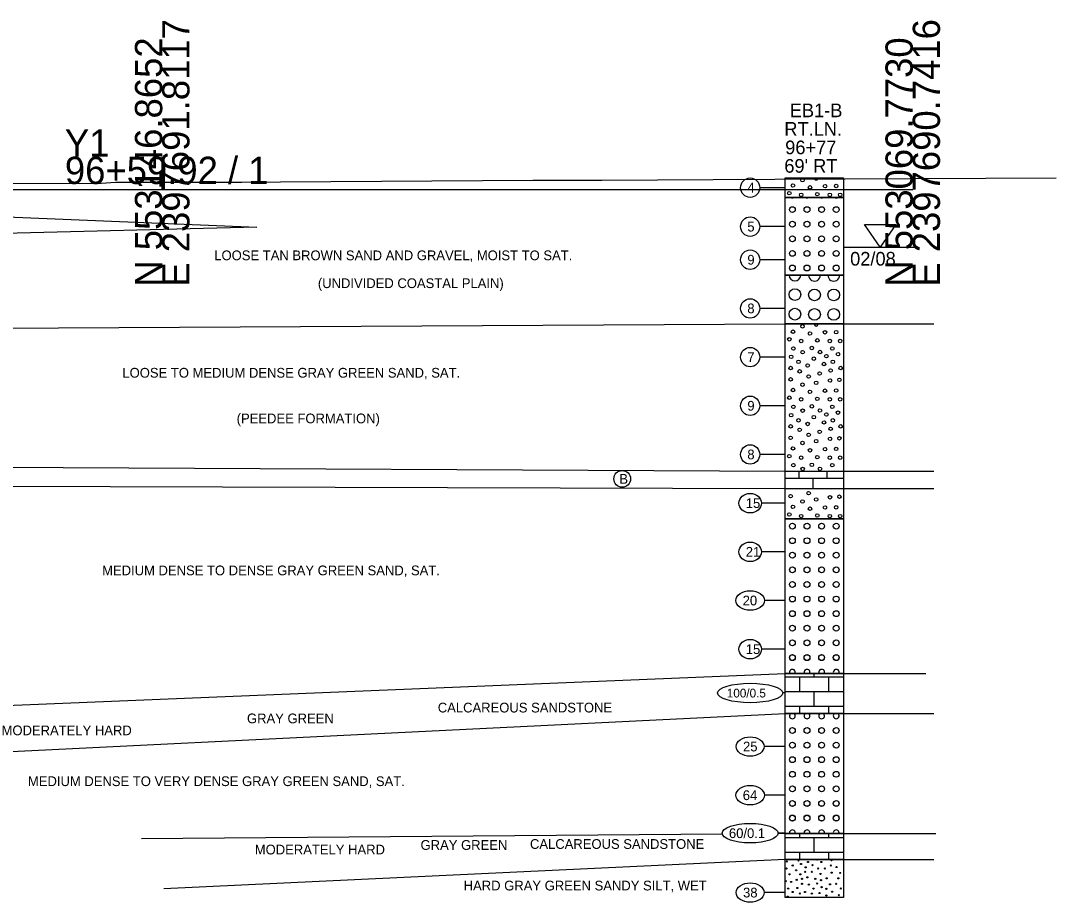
# Model space of a CAD drawing. Extents: x -26 to 164, y -74 to 517.
# Drawn here: x 57.6 to 164, y -73.2 to 17.3 of the extents above; entities that cross this region are included whole.
import ezdxf

# ---------------------------------------------------------------- set-up
doc = ezdxf.new("R2010")
doc.units = 0
for name, color, linetype in [('Exist XS Ground Line', 7, 'Continuous'), ('Old_Level_63', 7, 'Continuous'), ('Prop Road Sect_ Boring - Header Labels from Geopak', 7, 'Continuous'), ('Prop Road Sect_ Boring - Material (Outline)', 7, 'Continuous'), ('Prop Road Sect_ Boring - Peripheral (24 Hr GrdWtr Date)', 7, 'Continuous'), ('Prop Road Sect_ Boring - Peripheral (SPT Oval + Leader)', 7, 'Continuous'), ('Prop Road Sect_ Boring - Peripheral (SPT Tx)', 7, 'Continuous'), ('Prop Road Sect_ Material - Contact (General - Minor)', 7, 'Continuous'), ('Prop Road Sect_ Material - Tx (Composite Desc)', 7, 'Continuous'), ('Water Mark (24 Hr) Cell', 7, 'Continuous')]:
    doc.layers.add(name, color=color, linetype=linetype)

msp = doc.modelspace()

# ---------------------------------------------------------------- linework, layer by layer
at = {"layer": 'Exist XS Ground Line'}
for points in [[(135.07, 1.05), (163.98, 1.19)], [(0, 0.86), (2, 0.88), (15.97, 0.78), (18.54, 0.63), (22.6, 0.64), (32.39, 0.61), (35.94, 0.6), (40.49, 0.57), (65.87, 0.64), (67.35, 0.72), (72.13, 0.73), (80.32, 0.75), (84.27, 0.77), (110.22, 0.93), (117.29, 0.95), (128.72, 1.02), (135.07, 1.05)]]:
    msp.add_lwpolyline(points, dxfattribs=at)
at = {"layer": 'Old_Level_63'}
for p, q in [((72.13, 0), (72.13, 3.35)), ((0, 0), (72.13, 0)), ((72.13, 0), (149.23, 0))]:
    msp.add_line(p, q, dxfattribs=at)
at = {"layer": 'Prop Road Sect_ Boring - Material (Outline)'}
for p, q in [((136.13, -28.93), (142.12, -28.93)), ((136.13, -30.73), (142.12, -30.73)), ((139.12, -50.08), (139.12, -49.72)), ((136.13, -50.08), (142.12, -50.08)), ((137.62, -51.58), (137.62, -50.08)), ((140.62, -51.58), (140.62, -50.08)), ((142.12, -50.08), (142.13, -50.08)), ((136.13, -51.58), (142.12, -51.58)), ((139.12, -53.08), (139.12, -51.58)), ((142.12, -51.58), (142.13, -51.58)), ((136.13, -53.08), (142.12, -53.08)), ((137.62, -53.83), (137.62, -53.08)), ((140.62, -53.83), (140.62, -53.08)), ((142.12, -53.08), (142.13, -53.08)), ((142.12, -65.08), (142.13, -65.08)), ((136.13, -66.58), (142.12, -66.58)), ((137.62, -66.58), (137.62, -66.17)), ((139.12, -68.08), (139.12, -66.58)), ((140.62, -66.58), (140.62, -66.09)), ((142.12, -66.58), (142.13, -66.58)), ((136.13, -68.08), (142.12, -68.08)), ((137.62, -68.83), (137.62, -68.08)), ((140.62, -68.83), (140.62, -68.08)), ((142.12, -68.08), (142.13, -68.08))]:
    msp.add_line(p, q, dxfattribs=at)
for points in [[(136.13, 1.17), (142.13, 1.17), (142.13, -0.83), (136.13, -0.83)], [(136.13, -0.83), (142.13, -0.83), (142.13, -8.83), (136.13, -8.83)], [(136.13, -8.83), (142.13, -8.83), (142.13, -13.83), (136.13, -13.83)], [(136.13, -13.83), (142.13, -13.83), (142.13, -33.83), (136.13, -33.83)], [(136.13, -33.83), (142.13, -33.83), (142.13, -49.72), (136.13, -49.72)], [(136.13, -49.72), (142.13, -49.72), (142.13, -53.83), (136.13, -53.83)], [(136.13, -53.83), (142.13, -53.83), (142.13, -66.17), (136.13, -66.17)], [(136.13, -66.17), (142.13, -66.17), (142.13, -68.83), (136.13, -68.83)], [(136.13, -68.83), (142.13, -68.83), (142.13, -72.73), (136.13, -72.73)]]:
    msp.add_lwpolyline(points, close=True, dxfattribs=at)
for centre, radius in [((137.91, 0.94), 0.18), ((136.93, 0.39), 0.18), ((138.67, 0.2), 0.18), ((140.22, 0.32), 0.18), ((141.37, 0.34), 0.18), ((136.55, -0.39), 0.18), ((137.77, -0.56), 0.18), ((139.43, -0.5), 0.18), ((140.72, -0.56), 0.18), ((141.78, -0.56), 0.18), ((136.87, -2.08), 0.3), ((138.37, -2.08), 0.3), ((139.87, -2.08), 0.3), ((141.37, -2.08), 0.3), ((136.87, -3.58), 0.3), ((138.37, -3.58), 0.3), ((139.87, -3.58), 0.3), ((141.37, -3.58), 0.3), ((136.87, -5.08), 0.3), ((138.37, -5.08), 0.3), ((139.87, -5.08), 0.3), ((141.37, -5.08), 0.3), ((136.87, -6.58), 0.3), ((138.37, -6.58), 0.3), ((139.87, -6.58), 0.3), ((141.37, -6.58), 0.3), ((136.87, -8.08), 0.3), ((138.37, -8.08), 0.3), ((139.87, -8.08), 0.3), ((141.37, -8.08), 0.3), ((137.13, -10.81), 0.6), ((139.14, -10.84), 0.6), ((141.12, -10.84), 0.6), ((137.13, -12.82), 0.6), ((139.14, -12.85), 0.6), ((141.12, -12.85), 0.6), ((136.93, -14.62), 0.18), ((137.91, -14.07), 0.18), ((138.67, -14.8), 0.18), ((140.22, -14.68), 0.18), ((141.37, -14.67), 0.18), ((136.55, -15.4), 0.18), ((137.77, -15.57), 0.18), ((139.43, -15.51), 0.18), ((140.72, -15.57), 0.18), ((141.78, -15.57), 0.18), ((136.97, -16.34), 0.18), ((137.92, -16.73), 0.18), ((138.86, -16.29), 0.18), ((139.7, -16.71), 0.18), ((140.36, -17.13), 0.18), ((140.97, -16.34), 0.18), ((141.56, -16.93), 0.18), ((136.74, -17.21), 0.18), ((137.5, -17.72), 0.18), ((138.43, -18.1), 0.18), ((139.07, -17.4), 0.18), ((140.12, -17.94), 0.18), ((141.02, -17.72), 0.18), ((136.69, -18.35), 0.18), ((137.61, -18.7), 0.18), ((138.54, -19.22), 0.18), ((139.67, -18.91), 0.18), ((140.8, -18.6), 0.18), ((141.83, -18.35), 0.18), ((136.69, -19.52), 0.18), ((137.91, -20.07), 0.18), ((139.31, -19.87), 0.18), ((140.74, -19.63), 0.18), ((141.7, -19.57), 0.18), ((136.55, -21.4), 0.18), ((136.93, -20.61), 0.18), ((138.67, -20.8), 0.18), ((140.22, -20.68), 0.18), ((141.37, -20.66), 0.18), ((136.97, -22.34), 0.18), ((137.77, -21.56), 0.18), ((138.86, -22.29), 0.18), ((139.43, -21.51), 0.18), ((140.72, -21.56), 0.18), ((140.97, -22.34), 0.18), ((141.78, -21.56), 0.18), ((136.74, -23.2), 0.18), ((137.92, -22.73), 0.18), ((139.07, -23.4), 0.18), ((139.7, -22.71), 0.18), ((140.36, -23.12), 0.18), ((141.56, -22.93), 0.18), ((136.69, -24.35), 0.18), ((137.5, -23.72), 0.18), ((138.43, -24.1), 0.18), ((140.12, -23.94), 0.18), ((140.8, -24.59), 0.18), ((141.02, -23.72), 0.18), ((141.83, -24.35), 0.18), ((136.69, -25.52), 0.18), ((137.61, -24.7), 0.18), ((138.54, -25.22), 0.18), ((139.67, -24.91), 0.18), ((140.74, -25.63), 0.18), ((141.7, -25.57), 0.18), ((136.93, -26.61), 0.18), ((137.91, -26.06), 0.18), ((139.31, -25.87), 0.18), ((140.22, -26.68), 0.18), ((141.37, -26.66), 0.18), ((136.55, -27.4), 0.18), ((137.77, -27.56), 0.18), ((138.67, -26.8), 0.18), ((139.43, -27.51), 0.18), ((140.72, -27.56), 0.18), ((141.78, -27.56), 0.18), ((136.97, -28.33), 0.18), ((137.92, -28.72), 0.18), ((138.86, -28.29), 0.18), ((139.7, -28.7), 0.18), ((140.97, -28.33), 0.18), ((136.69, -31.51), 0.18), ((137.91, -32.06), 0.18), ((138.54, -31.21), 0.18), ((139.31, -31.86), 0.18), ((140.74, -31.63), 0.18), ((141.7, -31.57), 0.18), ((136.93, -32.61), 0.18), ((138.67, -32.8), 0.18), ((140.22, -32.68), 0.18), ((141.37, -32.66), 0.18), ((136.55, -33.39), 0.18), ((137.77, -33.56), 0.18), ((139.43, -33.5), 0.18), ((140.72, -33.56), 0.18), ((141.78, -33.56), 0.18), ((136.87, -34.59), 0.3), ((138.37, -34.59), 0.3), ((139.87, -34.59), 0.3), ((141.37, -34.59), 0.3), ((136.87, -36.09), 0.3), ((138.37, -36.09), 0.3), ((139.87, -36.09), 0.3), ((141.37, -36.09), 0.3), ((136.87, -37.58), 0.3), ((138.37, -37.58), 0.3), ((139.87, -37.58), 0.3), ((141.37, -37.58), 0.3), ((136.87, -39.08), 0.3), ((138.37, -39.08), 0.3), ((139.87, -39.08), 0.3), ((141.37, -39.08), 0.3), ((136.87, -40.58), 0.3), ((138.37, -40.58), 0.3), ((139.87, -40.58), 0.3), ((141.37, -40.58), 0.3), ((136.87, -42.08), 0.3), ((138.37, -42.08), 0.3), ((139.87, -42.08), 0.3), ((141.37, -42.08), 0.3), ((136.87, -43.58), 0.3), ((138.37, -43.58), 0.3), ((139.87, -43.58), 0.3), ((141.37, -43.58), 0.3), ((136.87, -45.08), 0.3), ((138.37, -45.08), 0.3), ((139.87, -45.08), 0.3), ((141.37, -45.08), 0.3), ((136.87, -46.58), 0.3), ((138.37, -46.58), 0.3), ((139.87, -46.58), 0.3), ((141.37, -46.58), 0.3), ((136.87, -48.08), 0.3), ((136.87, -48.1), 0.3), ((138.37, -48.08), 0.3), ((138.37, -48.1), 0.3), ((139.87, -48.08), 0.3), ((139.87, -48.1), 0.3), ((141.37, -48.08), 0.3), ((141.37, -48.1), 0.3), ((136.87, -55.58), 0.3), ((138.37, -55.58), 0.3), ((139.87, -55.58), 0.3), ((141.37, -55.58), 0.3), ((136.87, -57.08), 0.3), ((138.37, -57.08), 0.3), ((139.87, -57.08), 0.3), ((141.37, -57.08), 0.3), ((136.87, -58.58), 0.3), ((138.37, -58.58), 0.3), ((139.87, -58.58), 0.3), ((141.37, -58.58), 0.3), ((136.87, -60.08), 0.3), ((138.37, -60.08), 0.3), ((139.87, -60.08), 0.3), ((141.37, -60.08), 0.3), ((136.87, -61.58), 0.3), ((138.37, -61.58), 0.3), ((139.87, -61.58), 0.3), ((141.37, -61.58), 0.3), ((136.87, -63.07), 0.3), ((136.87, -63.08), 0.3), ((138.37, -63.07), 0.3), ((138.37, -63.08), 0.3), ((139.87, -63.07), 0.3), ((139.87, -63.08), 0.3), ((141.37, -63.07), 0.3), ((141.37, -63.08), 0.3), ((136.87, -64.57), 0.3), ((136.87, -64.59), 0.3), ((138.37, -64.57), 0.3), ((138.37, -64.59), 0.3), ((139.87, -64.57), 0.3), ((139.87, -64.59), 0.3), ((141.37, -64.57), 0.3), ((141.37, -64.59), 0.3), ((136.3, -69.04), 0.06), ((137.5, -68.93), 0.06), ((138.48, -69.09), 0.06), ((139.84, -69.09), 0.06), ((136.25, -69.75), 0.06), ((136.9, -69.45), 0.06), ((137.26, -69.94), 0.06), ((137.75, -69.29), 0.06), ((138.18, -70.1), 0.06), ((138.24, -69.64), 0.06), ((138.86, -70.1), 0.06), ((138.94, -69.42), 0.06), ((139.52, -69.75), 0.06), ((140.2, -69.75), 0.06), ((140.82, -69.45), 0.06), ((140.91, -70.19), 0.06), ((141.4, -69.61), 0.06), ((141.78, -70.21), 0.06), ((136.19, -71.06), 0.06), ((136.57, -70.35), 0.06), ((136.74, -71.14), 0.06), ((137.31, -70.92), 0.06), ((137.69, -70.35), 0.06), ((137.86, -70.81), 0.06), ((137.86, -71.33), 0.06), ((138.4, -70.67), 0.06), ((139.22, -70.81), 0.06), ((139.41, -71.3), 0.06), ((139.76, -70.32), 0.06), ((139.81, -70.95), 0.06), ((140.39, -70.76), 0.06), ((141.37, -71.33), 0.06), ((141.59, -70.76), 0.06), ((136.44, -71.82), 0.06), ((136.9, -72.17), 0.06), ((137.37, -71.76), 0.06), ((137.64, -72.32), 0.06), ((138.16, -72.17), 0.06), ((138.56, -71.41), 0.06), ((138.86, -72.34), 0.06), ((139.03, -71.82), 0.06), ((139.65, -72.28), 0.06), ((139.87, -71.68), 0.06), ((140.36, -71.84), 0.06), ((140.74, -71.38), 0.06), ((140.96, -72.14), 0.06), ((141.85, -71.81), 0.06), ((136.39, -72.65), 0.06), ((140.36, -72.53), 0.06), ((141.64, -72.5), 0.06)]:
    msp.add_circle(centre, radius, dxfattribs=at)
for centre, radius, start, end in [((139.31, 1.14), 0.18, 168.2251, 11.7749), ((136.87, -0.58), 0.3, 233.8794, 306.1206), ((138.37, -0.58), 0.3, 233.8794, 306.1206), ((139.87, -0.58), 0.3, 233.8794, 306.1206), ((141.37, -0.58), 0.3, 233.8794, 306.1206), ((137.13, -8.8), 0.6, 182.7567, 357.2433), ((139.14, -8.83), 0.6, 179.8909, 0.1091), ((141.12, -8.83), 0.6, 179.8909, 0.1091), ((139.31, -13.87), 0.18, 165.2817, 14.7183), ((136.87, -49.6), 0.3, 334.4403, 209.2197), ((138.37, -49.6), 0.3, 337.5104, 204.6559), ((139.87, -49.6), 0.3, 337.8029, 204.4844), ((141.37, -49.6), 0.3, 334.9558, 204.7524), ((136.87, -54.08), 0.3, 120.8079, 59.1921), ((138.37, -54.08), 0.3, 120.8079, 59.1921), ((139.87, -54.08), 0.3, 120.8079, 59.1921), ((141.37, -54.08), 0.3, 120.8079, 59.1921), ((136.87, -66.09), 0.3, 346.0959, 194.9222), ((138.37, -66.09), 0.3, 346.0471, 192.4516), ((139.87, -66.09), 0.3, 343.5414, 195.7376), ((141.37, -66.09), 0.3, 344.0701, 194.3296), ((136.87, -68.77), 0.06, 251.647, 288.353), ((139.41, -68.82), 0.06, 182.8163, 357.1837), ((140.88, -68.88), 0.06, 121.6941, 58.3059), ((141.67, -68.77), 0.06, 251.647, 288.353)]:
    msp.add_arc(centre, radius, start, end, dxfattribs=at)
at = {"layer": 'Prop Road Sect_ Boring - Peripheral (SPT Oval + Leader)'}
for p, q in [((136.13, 0.17), (133.51, 0.17)), ((136.13, -3.83), (133.51, -3.83)), ((136.13, -7.23), (133.51, -7.23)), ((136.13, -12.23), (133.51, -12.23)), ((136.13, -17.23), (133.51, -17.23)), ((136.13, -22.23), (133.51, -22.23)), ((136.13, -27.23), (133.51, -27.23)), ((136.13, -29.65), (141.88, -29.65)), ((137.57, -29.65), (137.57, -28.94)), ((139, -30.73), (139, -29.65)), ((140.44, -29.65), (140.44, -28.94)), ((141.88, -29.65), (142.12, -29.65)), ((136.13, -32.23), (133.68, -32.23)), ((136.13, -37.23), (133.68, -37.23)), ((136.13, -42.23), (134, -42.23)), ((136.13, -47.23), (133.68, -47.23)), ((136.13, -51.73), (135.87, -51.73)), ((136.13, -57.23), (133.96, -57.23)), ((136.13, -62.23), (133.98, -62.23)), ((136.13, -66.13), (135.41, -66.13)), ((136.13, -72.23), (133.96, -72.23))]:
    msp.add_line(p, q, dxfattribs=at)
for centre, major_axis, ratio in [((132.53, 0.17), (0, 1), 0.983465), ((132.53, -3.83), (0, 1), 0.983465), ((132.53, -7.23), (0, 1), 0.983465), ((132.53, -12.23), (0, 1), 0.983465), ((132.53, -17.23), (0, 1), 0.983465), ((132.53, -22.23), (0, 1), 0.983465), ((132.53, -27.23), (0, 1), 0.983465), ((132.53, -32.23), (1.15, 0), 0.870459), ((132.53, -37.23), (1.15, 0), 0.870459), ((132.53, -42.23), (1.47, 0), 0.679508), ((132.53, -47.23), (1.15, 0), 0.870459), ((132.53, -51.73), (3.35, 0), 0.298894), ((132.53, -57.23), (1.43, 0), 0.698186), ((132.53, -62.23), (1.46, 0), 0.686858), ((132.53, -66.13), (2.88, 0), 0.347089), ((132.53, -72.23), (1.43, 0), 0.698186)]:
    msp.add_ellipse(centre, major_axis=major_axis, ratio=ratio, dxfattribs=at)
at = {"layer": 'Prop Road Sect_ Material - Contact (General - Minor)'}
for p, q in [((22.13, -14.41), (136.13, -13.83)), ((142.13, -13.83), (151.41, -13.83)), ((22.19, -28.36), (136.13, -28.93)), ((142.12, -28.93), (151.4, -28.93)), ((22.19, -30.38), (136.13, -30.73)), ((142.12, -30.73), (151.4, -30.73)), ((22.13, -54.41), (136.13, -49.72)), ((142.13, -49.72), (150.57, -49.72)), ((22.13, -59.41), (136.13, -53.83)), ((142.13, -53.83), (151.41, -53.83)), ((129.66, -66.22), (70.01, -66.71)), ((136.13, -66.17), (135.41, -66.17)), ((142.13, -66.17), (151.59, -66.17)), ((136.13, -68.83), (72.29, -71.83)), ((142.13, -68.83), (151.41, -68.83))]:
    msp.add_line(p, q, dxfattribs=at)
msp.add_lwpolyline([(22.13, -1.41), (81.85, -3.9), (27.1, -5.27)], dxfattribs=at)
at = {"layer": 'Prop Road Sect_ Material - Tx (Composite Desc)'}
msp.add_circle((119.39, -29.74), 0.86, dxfattribs=at)
at = {"layer": 'Water Mark (24 Hr) Cell'}
for p, q in [((142.13, -5.93), (145.88, -5.93)), ((145.88, -5.93), (149.63, -5.93))]:
    msp.add_line(p, q, dxfattribs=at)
msp.add_lwpolyline([(144.27, -3.62), (147.49, -3.62), (145.88, -5.93)], close=True, dxfattribs=at)

# ---------------------------------------------------------------- texts
at = {"layer": 'Old_Level_63'}
for s, p in [('E 2397691.8117', (74.93, -10)), ('E 2397690.7416', (152.03, -10)), ('N 553146.8652', (72.13, -10)), ('N 553069.7730', (149.23, -10))]:
    msp.add_text(s, height=2.8, rotation=90, dxfattribs=at).set_placement(p)
for s, p in [('Y1', (62.13, 3.35)), ('96+59.92 / 1', (62.13, 0.55))]:
    msp.add_text(s, height=2.8, dxfattribs=at).set_placement(p)
at = {"layer": 'Prop Road Sect_ Boring - Header Labels from Geopak'}
for s, p in [('EB1-B', (136.6, 7.41)), ('RT.LN.', (136.04, 5.51)), ('96+77', (136.13, 3.61)), ("69' RT", (136.04, 1.71))]:
    msp.add_text(s, height=1.4, dxfattribs=at).set_placement(p)
at = {"layer": 'Prop Road Sect_ Boring - Peripheral (24 Hr GrdWtr Date)'}
msp.add_text('02/08', height=1.4, dxfattribs=at).set_placement((142.8, -7.83))
at = {"layer": 'Prop Road Sect_ Boring - Peripheral (SPT Tx)'}
for s, height, p in [('4', 1, (132.24, -0.33)), ('5', 1, (132.24, -4.33)), ('9', 1, (132.24, -7.73)), ('8', 1, (132.24, -12.73)), ('7', 1, (132.24, -17.73)), ('9', 1, (132.24, -22.73)), ('8', 1, (132.24, -27.73)), ('15', 1, (132.08, -32.73)), ('21', 1, (132.08, -37.73)), ('20', 1, (131.76, -42.73)), ('15', 1, (132.08, -47.73)), ('100/0.5', 0.9, (130.13, -52.19)), ('25', 1, (131.8, -57.73)), ('64', 1, (131.77, -62.73)), ('60/0.1', 1, (130.35, -66.63)), ('38', 1, (131.8, -72.73))]:
    msp.add_text(s, height=height, dxfattribs=at).set_placement(p)
at = {"layer": 'Prop Road Sect_ Material - Tx (Composite Desc)'}
for s, p in [('LOOSE TAN BROWN SAND AND GRAVEL, MOIST TO SAT.', (77.48, -7.28)), ('(UNDIVIDED COASTAL PLAIN)', (88.12, -10.14)), ('LOOSE TO MEDIUM DENSE GRAY GREEN SAND, SAT.', (68.04, -19.34)), ('(PEEDEE FORMATION)', (79.78, -24.03)), ('B', (119.09, -30.24)), ('MEDIUM DENSE TO DENSE GRAY GREEN SAND, SAT.', (65.96, -39.64)), ('CALCAREOUS SANDSTONE', (100.44, -53.73)), ('GRAY GREEN', (80.84, -54.84)), ('MODERATELY HARD', (55.63, -56.07)), ('MEDIUM DENSE TO VERY DENSE GRAY GREEN SAND, SAT.', (58.34, -61.29)), ('GRAY GREEN', (98.67, -67.84)), ('CALCAREOUS SANDSTONE', (109.91, -67.74)), ('MODERATELY HARD', (81.64, -68.31)), ('HARD GRAY GREEN SANDY SILT, WET', (103.1, -72.01))]:
    msp.add_text(s, height=1, dxfattribs=at).set_placement(p)

doc.saveas('drawing.dxf')
